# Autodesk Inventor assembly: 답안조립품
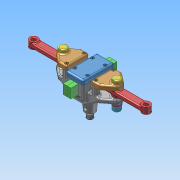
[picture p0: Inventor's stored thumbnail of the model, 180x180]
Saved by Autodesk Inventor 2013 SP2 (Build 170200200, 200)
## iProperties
Created: 2025-07
Part Number: 답안조립품
Document SubType Name: Assembly
Designer: a
Author: a
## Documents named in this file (11)
- C:\Users\a\Desktop\750703V1005\답안조립품.iam
- C:\Users\a\Desktop\750703V1005\본체.ipt
- C:\Users\a\Desktop\750703V1005\6각 구멍붙이 볼트 M3x10.ipt
- C:\Users\a\Desktop\750703V1005\6각 너트 M8.ipt
- C:\Users\a\Desktop\750703V1005\링크 커버.ipt
- C:\Users\a\Desktop\750703V1005\링크.ipt
- C:\Users\a\Desktop\750703V1005\스프링 와셔 M8.ipt
- C:\Users\a\Desktop\750703V1005\슬라이더 커버.ipt
- C:\Users\a\Desktop\750703V1005\슬라이더.ipt
- C:\Users\a\Desktop\750703V1005\평 와셔 M8.ipt
- C:\Users\a\Desktop\750703V1005\핀.ipt
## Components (12 placed, 3 different names)
1. 6각 구멍붙이 볼트 M3x10:1
2. 6각 너트 M8:1 — 각도:5
3. 핀:1 — 각도:3
4. 핀:2 — 각도:4
5. 6각 너트 M8:2 — 각도:6
6. 6각 구멍붙이 볼트 M3x10:2
7. 6각 구멍붙이 볼트 M3x10:3
8. 6각 구멍붙이 볼트 M3x10:4
9. 6각 구멍붙이 볼트 M3x10:5
10. 6각 구멍붙이 볼트 M3x10:6
11. 6각 구멍붙이 볼트 M3x10:7
12. 6각 구멍붙이 볼트 M3x10:8
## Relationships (4: Angle 4)
- 각도:3 [Angle]: 핀:1
- 각도:4 [Angle]: 핀:2
- 각도:5 [Angle]: 6각 너트 M8:1
- 각도:6 [Angle]: 6각 너트 M8:2
